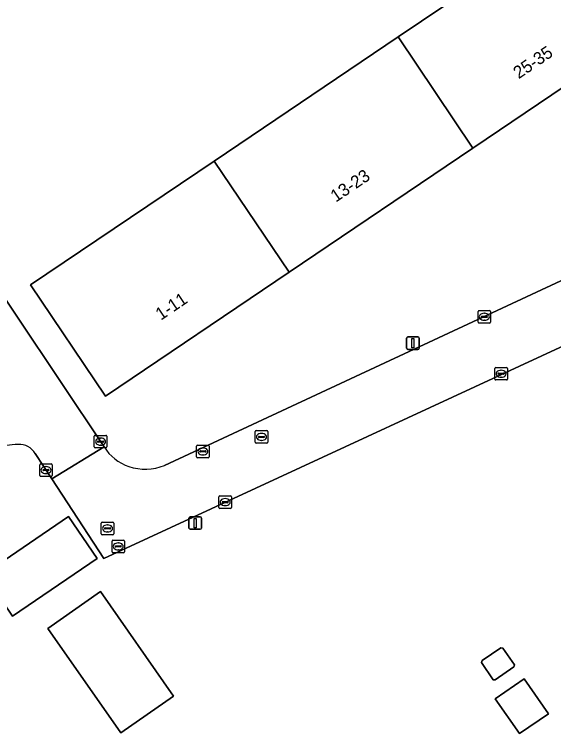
# Model space of a CAD drawing. Extents: x 157445 to 158888, y 383061 to 384688.
# Drawn here: x 157938.2 to 157981.3, y 383407 to 383464.4 of the extents above; entities that cross this region are included whole.
import ezdxf

# ---------------------------------------------------------------- set-up
doc = ezdxf.new("R2010")
doc.units = 0
for name, color, linetype in [('IMGEO_Brandkraan', 7, 'Continuous'), ('IMGEO_Erf', 7, 'Continuous'), ('IMGEO_Kolk', 7, 'Continuous'), ('IMGEO_Lichtmast', 7, 'Continuous'), ('IMGEO_Pand', 7, 'Continuous'), ('IMGEO_Pand_nummerreeks', 7, 'Continuous'), ('IMGEO_Rijbaan_lokaal_open', 7, 'Continuous'), ('IMGEO_Rioolput', 7, 'Continuous')]:
    doc.layers.add(name, color=color, linetype=linetype)

msp = doc.modelspace()

# ---------------------------------------------------------------- linework, layer by layer
at = {"layer": 'IMGEO_Brandkraan'}
for p, q in [((157957.465, 383430.237), (157957.465, 383431.089)), ((157957.54, 383431.163), (157958.392, 383431.163)), ((157958.466, 383431.089), (157958.466, 383430.237)), ((157957.724, 383430.657), (157957.724, 383430.669)), ((157958.162, 383430.62), (157957.764, 383430.62)), ((157957.767, 383430.706), (157958.165, 383430.706)), ((157957.953, 383430.943), (157957.978, 383430.943)), ((157958.208, 383430.669), (157958.208, 383430.657)), ((157958.392, 383430.163), (157957.54, 383430.163)), ((157957.976, 383430.383), (157957.951, 383430.383))]:
    msp.add_line(p, q, dxfattribs=at)
for points in [[(157957.465, 383430.237), (157957.465, 383431.089)], [(157957.54, 383431.163), (157958.392, 383431.163)], [(157958.466, 383431.089), (157958.466, 383430.237)], [(157958.392, 383430.163), (157957.54, 383430.163)]]:
    msp.add_lwpolyline(points, dxfattribs=at)
for centre, radius, start, end in [((157957.542, 383431.087), 0.0765, 91.55205, 178.44795), ((157957.542, 383431.087), 0.0765, 91.55205, 178.44795), ((157958.39, 383431.087), 0.0765, 1.55205, 88.44795), ((157958.39, 383431.087), 0.0765, 1.55205, 88.44795), ((157957.764, 383430.666), 0.0403, 85.87752, 175.75265), ((157957.761, 383430.656), 0.0366, 178.93798, 274.71019), ((157958.165, 383430.663), 0.043, 264.86636, 352.45326), ((157958.169, 383430.668), 0.0386, 1.73085, 96.63898), ((157957.542, 383430.239), 0.0765, 181.55205, 268.44795), ((157957.542, 383430.239), 0.0765, 181.55205, 268.44795), ((157958.39, 383430.239), 0.0765, 271.55205, 358.44795), ((157958.39, 383430.239), 0.0765, 271.55205, 358.44795)]:
    msp.add_arc(centre, radius, start, end, dxfattribs=at)
for centre, major_axis, ratio, start_param, end_param in [((157957.952, 383430.663), (-0.387, 0.002), 0.722429, 4.712389, 7.853982), ((157957.977, 383430.663), (-0.39, 0.002), 0.717154, 1.570796, 4.712389)]:
    msp.add_ellipse(centre, major_axis=major_axis, ratio=ratio, start_param=start_param, end_param=end_param, dxfattribs=at)
at = {"layer": 'IMGEO_Erf'}
for points in [[(157954.187, 383452.703), (157968.869, 383462.612), (157983.54, 383472.513), (157989.524, 383463.625), (157974.853, 383453.724), (157960.171, 383443.815), (157945.5, 383433.914), (157939.516, 383442.802)], [(157942.543, 383424.31), (157944.83, 383420.951), (157938.064, 383416.343), (157935.777, 383419.703)], [(157945.099, 383418.317), (157950.945, 383409.961), (157946.734, 383407.015), (157940.888, 383415.371)], [(157975.547, 383412.633), (157975.584, 383412.799), (157977.084, 383413.813), (157977.254, 383413.785), (157978.168, 383412.456), (157978.129, 383412.285), (157976.627, 383411.249), (157976.467, 383411.266)], [(157978.956, 383411.327), (157980.883, 383408.547), (157978.578, 383406.961), (157976.634, 383409.743)]]:
    msp.add_lwpolyline(points, close=True, dxfattribs=at)
for points in [[(157950.222, 383428.382), (157986.949, 383445.503), (157992.094, 383447.874), (157994.265, 383448.871), (157996.681, 383449.98), (157996.578, 383452.389)], [(157934.897, 383445.538), (157945.396, 383429.862)], [(157998.264, 383431.154), (158000, 383431.991), (158002.475, 383433.184), (157998.261, 383444.967), (157998.111, 383445.386), (157996.535, 383444.659), (157994.076, 383443.525), (157990.708, 383441.929), (157945.38, 383420.944), (157941.213, 383427.303), (157939.88, 383429.337)]]:
    msp.add_lwpolyline(points, dxfattribs=at)
for centre, radius, start, end in [((157938.372, 383426.76), 3.298, 87.19566, 120.20957), ((157938.642, 383428.634), 1.424, 29.57213, 94.37566), ((157948.568, 383431.834), 3.735, 211.86514, 251.16439), ((157948.678, 383432.264), 4.177, 251.63566, 291.68896)]:
    msp.add_arc(centre, radius, start, end, dxfattribs=at)
at = {"layer": 'IMGEO_Kolk'}
for p, q in [((157975.263, 383439.832), (157975.263, 383440.684)), ((157975.338, 383440.758), (157976.19, 383440.758)), ((157975.522, 383440.252), (157975.522, 383440.264)), ((157975.565, 383440.301), (157975.963, 383440.301)), ((157975.751, 383440.538), (157975.776, 383440.538)), ((157976.006, 383440.264), (157976.006, 383440.252)), ((157976.264, 383440.684), (157976.264, 383439.832)), ((157976.19, 383439.758), (157975.338, 383439.758)), ((157975.96, 383440.215), (157975.562, 383440.215)), ((157975.774, 383439.978), (157975.749, 383439.978)), ((157976.681, 383436.21), (157977.533, 383436.21)), ((157976.606, 383435.284), (157976.606, 383436.136)), ((157976.865, 383435.704), (157976.865, 383435.716)), ((157977.303, 383435.667), (157976.905, 383435.667)), ((157976.908, 383435.753), (157977.306, 383435.753)), ((157977.094, 383435.99), (157977.119, 383435.99)), ((157977.349, 383435.716), (157977.349, 383435.704)), ((157977.607, 383436.136), (157977.607, 383435.284)), ((157977.533, 383435.21), (157976.681, 383435.21)), ((157977.117, 383435.43), (157977.092, 383435.43)), ((157944.611, 383429.859), (157944.611, 383430.711)), ((157944.686, 383430.785), (157945.538, 383430.785)), ((157945.099, 383430.565), (157945.124, 383430.565)), ((157945.612, 383430.711), (157945.612, 383429.859)), ((157944.87, 383430.279), (157944.87, 383430.291)), ((157945.308, 383430.242), (157944.91, 383430.242)), ((157944.913, 383430.328), (157945.311, 383430.328)), ((157945.122, 383430.005), (157945.097, 383430.005)), ((157945.354, 383430.291), (157945.354, 383430.279)), ((157952.781, 383429.079), (157952.781, 383429.931)), ((157952.856, 383430.005), (157953.708, 383430.005)), ((157953.782, 383429.931), (157953.782, 383429.079)), ((157945.538, 383429.785), (157944.686, 383429.785)), ((157953.04, 383429.499), (157953.04, 383429.511)), ((157953.478, 383429.462), (157953.08, 383429.462)), ((157953.083, 383429.548), (157953.481, 383429.548)), ((157953.269, 383429.785), (157953.294, 383429.785)), ((157953.524, 383429.511), (157953.524, 383429.499)), ((157953.708, 383429.005), (157952.856, 383429.005)), ((157953.292, 383429.225), (157953.267, 383429.225)), ((157940.249, 383427.585), (157940.249, 383428.437)), ((157940.324, 383428.511), (157941.176, 383428.511)), ((157940.737, 383428.291), (157940.762, 383428.291)), ((157941.25, 383428.437), (157941.25, 383427.585)), ((157940.508, 383428.005), (157940.508, 383428.017)), ((157940.946, 383427.968), (157940.548, 383427.968)), ((157940.551, 383428.054), (157940.949, 383428.054)), ((157940.76, 383427.731), (157940.735, 383427.731)), ((157940.992, 383428.017), (157940.992, 383428.005)), ((157941.176, 383427.511), (157940.324, 383427.511)), ((157954.562, 383425.025), (157954.562, 383425.877)), ((157954.637, 383425.951), (157955.489, 383425.951)), ((157955.563, 383425.877), (157955.563, 383425.025)), ((157954.821, 383425.445), (157954.821, 383425.457)), ((157955.259, 383425.408), (157954.861, 383425.408)), ((157954.864, 383425.494), (157955.262, 383425.494)), ((157955.05, 383425.731), (157955.075, 383425.731)), ((157955.305, 383425.457), (157955.305, 383425.445)), ((157955.489, 383424.951), (157954.637, 383424.951)), ((157955.073, 383425.171), (157955.048, 383425.171))]:
    msp.add_line(p, q, dxfattribs=at)
for points in [[(157975.263, 383439.832), (157975.263, 383440.684)], [(157975.338, 383440.758), (157976.19, 383440.758)], [(157976.264, 383440.684), (157976.264, 383439.832)], [(157976.19, 383439.758), (157975.338, 383439.758)], [(157976.681, 383436.21), (157977.533, 383436.21)], [(157976.606, 383435.284), (157976.606, 383436.136)], [(157977.607, 383436.136), (157977.607, 383435.284)], [(157977.533, 383435.21), (157976.681, 383435.21)], [(157944.611, 383429.859), (157944.611, 383430.711)], [(157944.686, 383430.785), (157945.538, 383430.785)], [(157945.612, 383430.711), (157945.612, 383429.859)], [(157952.781, 383429.079), (157952.781, 383429.931)], [(157952.856, 383430.005), (157953.708, 383430.005)], [(157953.782, 383429.931), (157953.782, 383429.079)], [(157945.538, 383429.785), (157944.686, 383429.785)], [(157953.708, 383429.005), (157952.856, 383429.005)], [(157940.249, 383427.585), (157940.249, 383428.437)], [(157940.324, 383428.511), (157941.176, 383428.511)], [(157941.25, 383428.437), (157941.25, 383427.585)], [(157941.176, 383427.511), (157940.324, 383427.511)], [(157954.562, 383425.025), (157954.562, 383425.877)], [(157954.637, 383425.951), (157955.489, 383425.951)], [(157955.563, 383425.877), (157955.563, 383425.025)], [(157955.489, 383424.951), (157954.637, 383424.951)]]:
    msp.add_lwpolyline(points, dxfattribs=at)
for centre, radius, start, end in [((157975.34, 383440.682), 0.0765, 91.55205, 178.44795), ((157975.34, 383440.682), 0.0765, 91.55205, 178.44795), ((157975.562, 383440.261), 0.0403, 85.87752, 175.75265), ((157975.559, 383440.251), 0.0366, 178.93798, 274.71019), ((157975.963, 383440.258), 0.043, 264.86636, 352.45326), ((157975.967, 383440.263), 0.0386, 1.73085, 96.63898), ((157976.188, 383440.682), 0.0765, 1.55205, 88.44795), ((157976.188, 383440.682), 0.0765, 1.55205, 88.44795), ((157975.34, 383439.834), 0.0765, 181.55205, 268.44795), ((157975.34, 383439.834), 0.0765, 181.55205, 268.44795), ((157976.188, 383439.834), 0.0765, 271.55205, 358.44795), ((157976.188, 383439.834), 0.0765, 271.55205, 358.44795), ((157976.683, 383436.134), 0.0765, 91.55205, 178.44795), ((157976.683, 383436.134), 0.0765, 91.55205, 178.44795), ((157977.531, 383436.134), 0.0765, 1.55205, 88.44795), ((157977.531, 383436.134), 0.0765, 1.55205, 88.44795), ((157976.905, 383435.713), 0.0403, 85.87752, 175.75265), ((157976.902, 383435.703), 0.0366, 178.93798, 274.71019), ((157977.306, 383435.71), 0.043, 264.86636, 352.45326), ((157977.31, 383435.715), 0.0386, 1.73085, 96.63898), ((157976.683, 383435.286), 0.0765, 181.55205, 268.44795), ((157976.683, 383435.286), 0.0765, 181.55205, 268.44795), ((157977.531, 383435.286), 0.0765, 271.55205, 358.44795), ((157977.531, 383435.286), 0.0765, 271.55205, 358.44795), ((157944.688, 383430.709), 0.0765, 91.55205, 178.44795), ((157944.688, 383430.709), 0.0765, 91.55205, 178.44795), ((157945.536, 383430.709), 0.0765, 1.55205, 88.44795), ((157945.536, 383430.709), 0.0765, 1.55205, 88.44795), ((157944.91, 383430.288), 0.0403, 85.87752, 175.75265), ((157944.907, 383430.278), 0.0366, 178.93798, 274.71019), ((157945.311, 383430.285), 0.043, 264.86636, 352.45326), ((157945.315, 383430.29), 0.0386, 1.73085, 96.63898), ((157952.858, 383429.929), 0.0765, 91.55205, 178.44795), ((157952.858, 383429.929), 0.0765, 91.55205, 178.44795), ((157953.706, 383429.929), 0.0765, 1.55205, 88.44795), ((157953.706, 383429.929), 0.0765, 1.55205, 88.44795), ((157944.688, 383429.861), 0.0765, 181.55205, 268.44795), ((157944.688, 383429.861), 0.0765, 181.55205, 268.44795), ((157945.536, 383429.861), 0.0765, 271.55205, 358.44795), ((157945.536, 383429.861), 0.0765, 271.55205, 358.44795), ((157953.08, 383429.508), 0.0403, 85.87752, 175.75265), ((157953.077, 383429.498), 0.0366, 178.93798, 274.71019), ((157953.481, 383429.505), 0.043, 264.86636, 352.45326), ((157953.485, 383429.51), 0.0386, 1.73085, 96.63898), ((157952.858, 383429.081), 0.0765, 181.55205, 268.44795), ((157952.858, 383429.081), 0.0765, 181.55205, 268.44795), ((157953.706, 383429.081), 0.0765, 271.55205, 358.44795), ((157953.706, 383429.081), 0.0765, 271.55205, 358.44795), ((157940.326, 383428.435), 0.0765, 91.55205, 178.44795), ((157940.326, 383428.435), 0.0765, 91.55205, 178.44795), ((157941.174, 383428.435), 0.0765, 1.55205, 88.44795), ((157941.174, 383428.435), 0.0765, 1.55205, 88.44795), ((157940.548, 383428.014), 0.0403, 85.87752, 175.75265), ((157940.545, 383428.004), 0.0366, 178.93798, 274.71019), ((157940.949, 383428.011), 0.043, 264.86636, 352.45326), ((157940.953, 383428.016), 0.0386, 1.73085, 96.63898), ((157940.326, 383427.587), 0.0765, 181.55205, 268.44795), ((157940.326, 383427.587), 0.0765, 181.55205, 268.44795), ((157941.174, 383427.587), 0.0765, 271.55205, 358.44795), ((157941.174, 383427.587), 0.0765, 271.55205, 358.44795), ((157954.639, 383425.875), 0.0765, 91.55205, 178.44795), ((157954.639, 383425.875), 0.0765, 91.55205, 178.44795), ((157955.487, 383425.875), 0.0765, 1.55205, 88.44795), ((157955.487, 383425.875), 0.0765, 1.55205, 88.44795), ((157954.861, 383425.454), 0.0403, 85.87752, 175.75265), ((157954.858, 383425.444), 0.0366, 178.93798, 274.71019), ((157955.262, 383425.451), 0.043, 264.86636, 352.45326), ((157955.266, 383425.456), 0.0386, 1.73085, 96.63898), ((157954.639, 383425.027), 0.0765, 181.55205, 268.44795), ((157954.639, 383425.027), 0.0765, 181.55205, 268.44795), ((157955.487, 383425.027), 0.0765, 271.55205, 358.44795), ((157955.487, 383425.027), 0.0765, 271.55205, 358.44795)]:
    msp.add_arc(centre, radius, start, end, dxfattribs=at)
for centre, major_axis, ratio, start_param, end_param in [((157975.75, 383440.258), (-0.387, 0.002), 0.722429, 4.712389, 7.853982), ((157975.775, 383440.258), (-0.39, 0.002), 0.717154, 1.570796, 4.712389), ((157977.093, 383435.71), (-0.387, 0.002), 0.722429, 4.712389, 7.853982), ((157977.118, 383435.71), (-0.39, 0.002), 0.717154, 1.570796, 4.712389), ((157945.098, 383430.285), (-0.387, 0.002), 0.722429, 4.712389, 7.853982), ((157945.123, 383430.285), (-0.39, 0.002), 0.717154, 1.570796, 4.712389), ((157953.268, 383429.505), (-0.387, 0.002), 0.722429, 4.712389, 7.853982), ((157953.293, 383429.505), (-0.39, 0.002), 0.717154, 1.570796, 4.712389), ((157940.736, 383428.011), (-0.387, 0.002), 0.722429, 4.712389, 7.853982), ((157940.761, 383428.011), (-0.39, 0.002), 0.717154, 1.570796, 4.712389), ((157955.049, 383425.451), (-0.387, 0.002), 0.722429, 4.712389, 7.853982), ((157955.074, 383425.451), (-0.39, 0.002), 0.717154, 1.570796, 4.712389)]:
    msp.add_ellipse(centre, major_axis=major_axis, ratio=ratio, start_param=start_param, end_param=end_param, dxfattribs=at)
at = {"layer": 'IMGEO_Lichtmast'}
for p, q in [((157969.559, 383437.755), (157969.559, 383438.555)), ((157969.559, 383438.555), (157969.559, 383437.755)), ((157969.659, 383438.655), (157970.449, 383438.655)), ((157970.449, 383438.655), (157969.659, 383438.655)), ((157970.549, 383438.555), (157970.549, 383437.755)), ((157970.549, 383437.755), (157970.549, 383438.555)), ((157970.449, 383437.655), (157969.659, 383437.655)), ((157969.659, 383437.655), (157970.449, 383437.655)), ((157952.172, 383423.382), (157952.172, 383424.182)), ((157952.172, 383424.182), (157952.172, 383423.382)), ((157952.272, 383424.282), (157953.062, 383424.282)), ((157953.062, 383424.282), (157952.272, 383424.282)), ((157953.162, 383424.182), (157953.162, 383423.382)), ((157953.162, 383423.382), (157953.162, 383424.182)), ((157953.062, 383423.282), (157952.272, 383423.282)), ((157952.272, 383423.282), (157953.062, 383423.282))]:
    msp.add_line(p, q, dxfattribs=at)
for points in [[(157969.979, 383438.53), (157970.129, 383438.53), (157970.129, 383437.78), (157969.979, 383437.78), (157969.979, 383438.53)], [(157952.592, 383424.157), (157952.742, 383424.157), (157952.742, 383423.407), (157952.592, 383423.407), (157952.592, 383424.157)]]:
    msp.add_lwpolyline(points, dxfattribs=at)
for centre, start, end in [((157969.659, 383438.555), 90, 180), ((157969.659, 383438.555), 90, 180), ((157970.449, 383438.555), 0, 90), ((157970.449, 383438.555), 360, 90), ((157969.659, 383437.755), 180, 270), ((157969.659, 383437.755), 180, 270), ((157970.449, 383437.755), 270, 0), ((157970.449, 383437.755), 270, 0), ((157952.272, 383424.182), 90, 180), ((157952.272, 383424.182), 90, 180), ((157953.062, 383424.182), 0, 90), ((157953.062, 383424.182), 360, 90), ((157952.272, 383423.382), 180, 270), ((157952.272, 383423.382), 180, 270), ((157953.062, 383423.382), 270, 0), ((157953.062, 383423.382), 270, 0)]:
    msp.add_arc(centre, 0.1, start, end, dxfattribs=at)
at = {"layer": 'IMGEO_Pand'}
for points in [[(157974.853, 383453.724), (157989.524, 383463.625), (157983.54, 383472.513), (157968.869, 383462.612)], [(157974.853, 383453.724), (157968.869, 383462.612), (157954.187, 383452.703), (157960.171, 383443.815)], [(157954.187, 383452.703), (157939.516, 383442.802), (157945.5, 383433.914), (157960.171, 383443.815)], [(157938.064, 383416.343), (157944.83, 383420.951), (157942.543, 383424.31), (157935.777, 383419.703)], [(157946.734, 383407.015), (157950.945, 383409.961), (157945.099, 383418.317), (157940.888, 383415.371)], [(157976.627, 383411.249), (157978.129, 383412.285), (157978.168, 383412.456), (157977.254, 383413.785), (157977.084, 383413.813), (157975.584, 383412.799), (157975.547, 383412.633), (157976.467, 383411.266)], [(157978.578, 383406.961), (157980.883, 383408.547), (157978.956, 383411.327), (157976.634, 383409.743)]]:
    msp.add_lwpolyline(points, close=True, dxfattribs=at)
at = {"layer": 'IMGEO_Rijbaan_lokaal_open'}
for points in [[(157939.88, 383429.337), (157941.213, 383427.303), (157945.396, 383429.862), (157934.897, 383445.538), (157921.861, 383464.881)], [(157990.708, 383441.929), (157994.076, 383443.525), (157992.094, 383447.874), (157986.949, 383445.503), (157950.222, 383428.382)], [(157945.396, 383429.862), (157941.213, 383427.303), (157945.38, 383420.944), (157990.708, 383441.929)]]:
    msp.add_lwpolyline(points, dxfattribs=at)
for centre, radius, start, end in [((157938.372, 383426.76), 3.298, 87.19566, 120.20957), ((157938.642, 383428.634), 1.424, 29.57213, 94.37566), ((157948.568, 383431.834), 3.735, 211.86514, 251.16439), ((157948.678, 383432.264), 4.177, 251.63566, 291.68896)]:
    msp.add_arc(centre, radius, start, end, dxfattribs=at)
at = {"layer": 'IMGEO_Rioolput'}
for p, q in [((157945.166, 383422.927), (157945.166, 383423.779)), ((157945.241, 383423.853), (157946.093, 383423.853)), ((157945.654, 383423.633), (157945.679, 383423.633)), ((157946.167, 383423.779), (157946.167, 383422.927)), ((157945.425, 383423.347), (157945.425, 383423.359)), ((157945.863, 383423.31), (157945.465, 383423.31)), ((157945.468, 383423.396), (157945.866, 383423.396)), ((157945.677, 383423.073), (157945.652, 383423.073)), ((157945.909, 383423.359), (157945.909, 383423.347)), ((157946.093, 383422.853), (157945.241, 383422.853)), ((157946.024, 383421.489), (157946.024, 383422.341)), ((157946.099, 383422.415), (157946.951, 383422.415)), ((157946.283, 383421.909), (157946.283, 383421.921)), ((157946.721, 383421.872), (157946.323, 383421.872)), ((157946.326, 383421.958), (157946.724, 383421.958)), ((157946.512, 383422.195), (157946.537, 383422.195)), ((157946.767, 383421.921), (157946.767, 383421.909)), ((157947.025, 383422.341), (157947.025, 383421.489)), ((157946.951, 383421.415), (157946.099, 383421.415)), ((157946.535, 383421.635), (157946.51, 383421.635))]:
    msp.add_line(p, q, dxfattribs=at)
for points in [[(157945.166, 383422.927), (157945.166, 383423.779)], [(157945.241, 383423.853), (157946.093, 383423.853)], [(157946.167, 383423.779), (157946.167, 383422.927)], [(157946.093, 383422.853), (157945.241, 383422.853)], [(157946.024, 383421.489), (157946.024, 383422.341)], [(157946.099, 383422.415), (157946.951, 383422.415)], [(157947.025, 383422.341), (157947.025, 383421.489)], [(157946.951, 383421.415), (157946.099, 383421.415)]]:
    msp.add_lwpolyline(points, dxfattribs=at)
for centre, radius, start, end in [((157945.243, 383423.777), 0.0765, 91.55205, 178.44795), ((157945.243, 383423.777), 0.0765, 91.55205, 178.44795), ((157946.091, 383423.777), 0.0765, 1.55205, 88.44795), ((157946.091, 383423.777), 0.0765, 1.55205, 88.44795), ((157945.465, 383423.356), 0.0403, 85.87752, 175.75265), ((157945.462, 383423.346), 0.0366, 178.93798, 274.71019), ((157945.866, 383423.353), 0.043, 264.86636, 352.45326), ((157945.87, 383423.358), 0.0386, 1.73085, 96.63898), ((157945.243, 383422.929), 0.0765, 181.55205, 268.44795), ((157945.243, 383422.929), 0.0765, 181.55205, 268.44795), ((157946.091, 383422.929), 0.0765, 271.55205, 358.44795), ((157946.091, 383422.929), 0.0765, 271.55205, 358.44795), ((157946.101, 383422.339), 0.0765, 91.55205, 178.44795), ((157946.101, 383422.339), 0.0765, 91.55205, 178.44795), ((157946.323, 383421.918), 0.0403, 85.87752, 175.75265), ((157946.32, 383421.908), 0.0366, 178.93798, 274.71019), ((157946.724, 383421.915), 0.043, 264.86636, 352.45326), ((157946.728, 383421.92), 0.0386, 1.73085, 96.63898), ((157946.949, 383422.339), 0.0765, 1.55205, 88.44795), ((157946.949, 383422.339), 0.0765, 1.55205, 88.44795), ((157946.101, 383421.491), 0.0765, 181.55205, 268.44795), ((157946.101, 383421.491), 0.0765, 181.55205, 268.44795), ((157946.949, 383421.491), 0.0765, 271.55205, 358.44795), ((157946.949, 383421.491), 0.0765, 271.55205, 358.44795)]:
    msp.add_arc(centre, radius, start, end, dxfattribs=at)
for centre, major_axis, ratio, start_param, end_param in [((157945.653, 383423.353), (-0.387, 0.002), 0.722429, 4.712389, 7.853982), ((157945.678, 383423.353), (-0.39, 0.002), 0.717154, 1.570796, 4.712389), ((157946.511, 383421.915), (-0.387, 0.002), 0.722429, 4.712389, 7.853982), ((157946.536, 383421.915), (-0.39, 0.002), 0.717154, 1.570796, 4.712389)]:
    msp.add_ellipse(centre, major_axis=major_axis, ratio=ratio, start_param=start_param, end_param=end_param, dxfattribs=at)

# ---------------------------------------------------------------- texts
at = {"layer": 'IMGEO_Pand_nummerreeks'}
for s, p in [('25-35', (157978.503, 383459.227)), ('13-23', (157963.902, 383449.373)), ('1-11', (157949.926, 383439.941))]:
    msp.add_text(s, height=1, rotation=34.0147, dxfattribs=at).set_placement(p)

doc.saveas('drawing.dxf')
